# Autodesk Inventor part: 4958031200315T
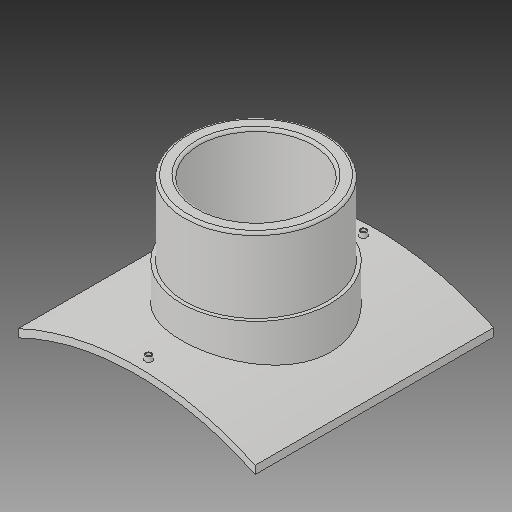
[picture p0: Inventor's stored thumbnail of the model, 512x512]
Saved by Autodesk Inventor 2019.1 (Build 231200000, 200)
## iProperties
Created: 2017-10
Part Number: 4958031200315T
Material: Generic
Description: PLASSON BRANCH SADDLE  1200x315
Document SubType Name: Modeling
Designer: KIM
Mass: 2754.05 g
Surface Area: 3037.44 cm^2
Volume: 2754.05 cm^3
Density: 1 g/cm^3
Appearance: Default
Author: KIM
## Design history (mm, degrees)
derived "495803.ipt"
feature "Solid1::495803.ipt"
tag "TaggingFeature1"
body "Solid1"
other parameters: "d1" = 16, "d2" = 526, "d4" = 0, "d12" = 625.6, "d13" = 14, "d14" = 238.5, "d16" = 5 deg, "d18" = 4, "d19" = 14, "d20" = 0, "d21" = 3, "d22" = 0, "d23" = 852, "d24" = 330.75, "d25" = 16, "d26" = 252, "d28" = 0, "d29" = 9.6, "d31" = 0, "d32" = 118, "d33" = 0, "d34" = 12, "d36" = 315, "d37" = 165.2, "d38" = 0, "d39" = 6, "d_1" = 315, "B_" = 526, "H_" = 236, "x_" = 16, "D_" = 16
